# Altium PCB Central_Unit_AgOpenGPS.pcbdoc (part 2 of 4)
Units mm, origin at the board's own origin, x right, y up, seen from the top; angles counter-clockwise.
Board outline 200.19 x 122.57 mm, 2 copper layers (Top Layer, Bottom Layer); 271 components, 213 nets, 1023 pads, 412 vias.
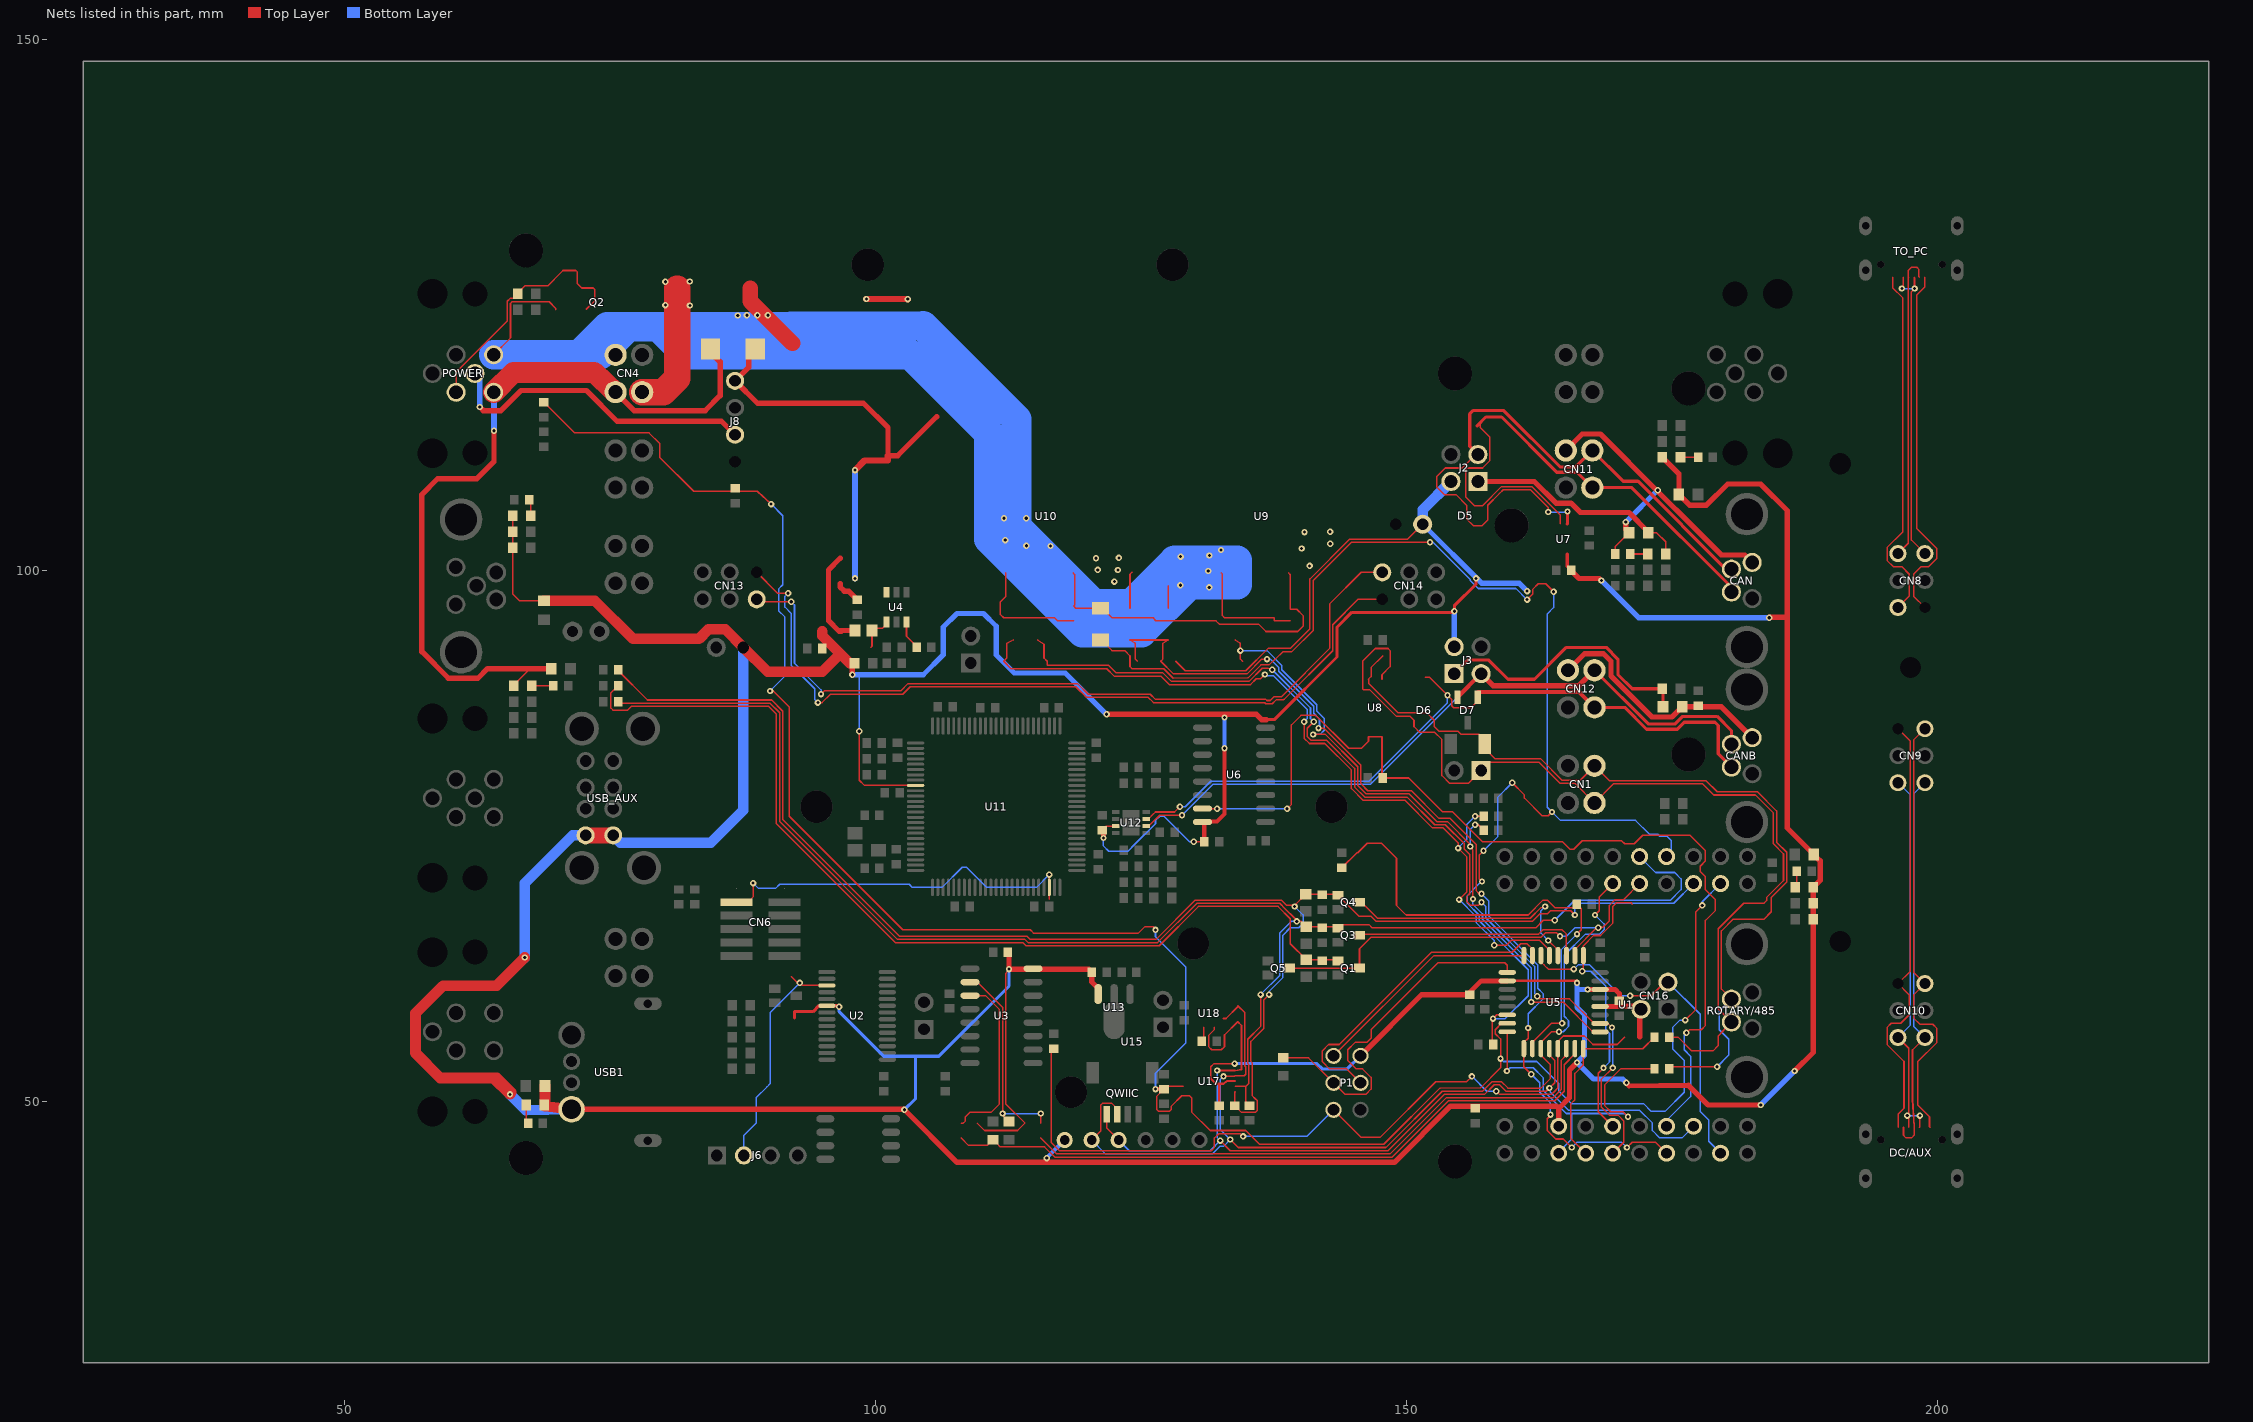
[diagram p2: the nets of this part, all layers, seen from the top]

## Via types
v1: diameter 0.6, hole 0.3, Top Layer to Bottom Layer, 411 vias
v2: diameter 0.61, hole 0.305, Top Layer to Bottom Layer, 1 vias

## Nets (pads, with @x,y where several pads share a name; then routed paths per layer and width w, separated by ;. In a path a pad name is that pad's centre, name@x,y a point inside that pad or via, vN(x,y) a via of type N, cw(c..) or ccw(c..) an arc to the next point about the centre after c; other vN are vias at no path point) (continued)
+5V: 5V.2 C2.1 C4.1 C11.1 C14.1 C22.1 C26.1 C34.1 C35.1 C40.1 C53.1 C56.1 CHA.2 CHB.2 CN7.1 CN16.2 F1.2 F5.1 F6.1 F7.1 FGNSS.1 FROT.1 FSER.1 FWAS.1 J1.2 J2.2 J3.2 L8.2 P1.2 R6.2 R22.2 R23.2 R48.1 U1.31 U2.20 U3.16 U5.4 U5.6 U5.18 U6.16 U7.3 U11.9 U12.3 U13.3 U15.1 U17.8 USB1.1 USB_AUX.1 USB_AUX.5 WAS1.2 WAS2.2 | length 676.7
  Top Layer w0.145: FWAS.1@65.837,105.166 65.837,97.815 66.488,97.165 F5.1@68.786,97.165 ; FGNSS.1@68.837,49.666 68.887,49.716 F1.2@68.887,51.466 ; v1(98.486,84.866) 98.486,80.267 98.987,79.766 U11.9@103.787,79.766 ; R22.2@109.587,47.966 110.287,47.266 110.487,47.266 ; C40.1@121.387,75.566 121.757,75.936 U12.3@122.655,75.936 ; R48.1@128.287,91.466 129.187,90.566 134.887,90.566 136.988,92.667 139.088,92.667 140.937,94.516 140.937,99.218 144.687,102.967 150.158,102.967 J1.2@151.557,104.366 ; v1(129.987,74.466) C4.1@130.987,74.466 ; 131.588,52.167 131.588,53.266 131.887,53.566 v1(133.837,53.566) ; CHB.2@188.337,67.166 188.337,70.166 188.887,70.716 188.887,72.766 F6.1@188.387,73.266
  Top Layer w0.15: 110.487,47.266 113.388,47.266 R23.2@114.087,47.966 112.286,49.766 112.287,62.066 v1(112.587,62.466) 112.632,62.511 U3.16@114.859,62.511
  Top Layer w0.2: 131.587,52.166 132.087,51.666 132.787,51.666 133.138,51.917 U17.8@133.89,51.917 ; C14.1@132.387,49.616 132.387,51.635 132.419,51.666
  Top Layer w0.25: U5.18@159.518,61.356 166.089,61.356 v1(166.087,61.166)
  Top Layer w0.3: C26.1@92.387,57.866 92.388,58.466 94.138,58.466 94.689,59.02 U2.20@95.442,59.018 ; U2.20@95.442,59.018 96.541,59.019 96.587,58.972 v1(96.587,58.916) ; 136.924,85.966 137.587,85.966 143.488,91.867 143.488,94.666 144.887,96.065 148.588,96.065 154.437,96.065 v1(154.537,96.166) 154.537,96.687 156.586,98.737 v1(156.587,99.266) ; U7.3@165.167,101.533 165.167,100.386 C2.1@165.537,100.016
  Top Layer w0.4: U6.16@130.815,76.321 U6.16@130.987,76.149 ; C4.1@130.987,74.466 U6.16@130.987,76.149 ; v1(132.887,83.266) 132.888,77.066 132.187,76.365 130.988,76.365 U6.16@130.988,76.149
  Top Layer w0.45: C22.1@155.987,60.066 155.987,60.267 157.077,61.356 U5.18@159.518,61.356 ; U5.4@168.255,58.948 170.087,58.948 170.087,60.166 169.688,60.546 ; U5.6@168.255,60.546 169.667,60.546
  Top Layer w0.5: 70.087,49.167 70.386,49.266 102.688,49.266 107.686,44.267 148.888,44.267 154.186,49.566 164.148,49.566 164.366,49.347 ; v1(97.837,90.191) 5V.2@97.837,91.266 ; C35.1@112.487,64.066 112.587,63.966 v1(112.587,62.466) 120.087,62.466 C53.1@120.387,62.166 ; C53.1@120.386,62.167 120.386,61.265 120.988,60.665 U13.3@120.988,60.114 ; C40.1@121.387,75.566 121.487,75.466 v1(121.487,74.816) ; v1(121.787,86.466) 135.887,86.466 136.387,85.966 136.837,85.966 ; P1.2@145.699,54.298 151.467,60.066 C22.1@155.987,60.066 ; U1.31@164.366,47.666 164.366,49.347 ; C2.1@165.537,100.016 166.287,99.266 168.187,99.266 v1(168.387,99.066) ; v1@166.086,53.665 165.388,52.967 165.388,50.366 164.366,49.347 ; v1(167.087,60.547) U5.6@168.256,60.547 ; C34.1@170.087,59.466 170.087,58.966 171.885,58.966 171.986,58.865 171.986,56.065 ; v1(170.737,51.766) 170.987,51.466 176.586,51.516 178.438,49.667 v1(183.387,49.666) ; FSER.1@174.137,110.666 175.687,109.116 F7.1@175.687,107.166 176.688,106.167 178.288,106.167 180.287,108.166 183.388,108.166 185.888,105.667 185.888,75.766 F6.1@188.387,73.266 188.987,72.666 188.987,70.816 188.337,70.166 188.337,54.616 ; v1(184.187,95.566) 184.23,95.608 185.888,95.608 ; v1(186.587,52.866) 188.337,54.616 ; 188.337,55.481 188.337,54.616
  Top Layer w1: 63.478,52.215 64.038,52.215 v1(65.587,50.666) ; v1@65.687,50.866 64.339,52.215 59.038,52.215 56.688,54.564 56.688,58.316 59.287,60.917 64.339,60.917 v1(66.987,63.566) ; F5.1@68.786,97.165 73.587,97.165 77.186,93.566 83.386,93.566 84.288,94.465 85.858,94.465 CN7.1@87.557,92.766 89.858,90.465 94.986,90.465 96.688,92.167 ; F1.2@68.887,51.466 68.888,49.566 USB1.1@71.387,49.266 ; 94.987,94.266 94.987,93.866 96.687,92.166 ; 5V.2@97.837,91.266 97.587,91.266 96.687,92.166
  Top Layer w1.5: USB_AUX.1@72.712,75.066 USB_AUX.5@75.313,75.066
  Bottom Layer w0.145: v1(98.486,84.866) 98.486,90.191 ; v1(121.487,74.816) 121.487,74.066 121.987,73.566 123.787,73.566 124.487,74.266 126.387,76.166 126.387,76.466 126.787,76.866 127.187,76.866 127.587,76.466 129.587,74.466 v1(129.987,74.466)
  Bottom Layer w0.3: v1(96.587,58.916) 96.587,58.466 100.787,54.266 105.987,54.266 112.587,60.866 v1(112.587,62.466) ; v1(102.737,49.216) 103.787,50.266 103.787,54.266 ; v1(133.837,53.566) 141.587,53.566 142.087,53.066 144.467,53.066 P1.2@145.699,54.298
  Bottom Layer w0.4: v1(116.137,44.666) U15.1@117.837,46.366 ; v1(132.887,83.266) v1(132.887,86.166)
  Bottom Layer w0.5: v1@97.836,90.19 104.514,90.19 106.388,92.065 106.388,94.666 107.686,95.966 110.188,95.966 111.387,94.765 111.387,92.065 113.086,90.366 117.887,90.366 v1(121.787,86.466) ; J1.2@151.557,104.366 157.107,98.816 160.637,98.816 v1(161.387,98.066) ; J3.2@154.517,92.836 154.537,92.856 v1(154.537,96.166) ; 166.087,60.566 v1(166.087,61.166) ; v1(167.087,60.547) 166.205,60.546 166.086,60.665 166.086,58.867 166.787,58.166 166.787,54.366 166.086,53.665 167.635,52.116 170.386,52.116 v1(170.737,51.766) ; v1(168.387,99.066) 171.887,95.566 v1(184.187,95.566) ; v1(183.387,49.666) v1@186.587,52.866
  Bottom Layer w1: v1(65.587,50.666) 67.087,49.166 USB1.1@71.387,49.266 ; v1(66.987,63.566) 66.988,70.566 71.486,75.065 USB_AUX.1@72.712,75.066 ; USB_AUX.5@75.311,75.065 75.987,74.366 84.486,74.366 87.557,77.437 CN7.1@87.557,92.766 ; J1.2@151.557,104.366 151.557,105.736 J2.2@154.217,108.396
  other v1: 166.087,53.666
+BATT: CN4.2 D3.2 F4.1 FINP.1 POWER.1 | length 76.3
  Top Layer w0.145: FINP.1@65.937,89.166 65.937,89.216 67.487,90.766 F4.1@69.487,90.766
  Top Layer w0.5: v1(64.087,113.166) 64.087,110.267 62.487,108.666 58.786,108.666 57.288,107.165 57.288,92.367 59.787,89.865 62.586,89.865 63.488,90.767 F4.1@69.487,90.766 ; CN4.2@75.538,116.817 77.288,115.067 83.978,115.067 85.388,116.477 85.388,119.665 84.486,120.566 D3.2@84.486,121.067
  Top Layer w2: POWER.1@64.054,116.797 65.924,118.666 73.513,118.666 CN4.2@75.487,116.817
  Bottom Layer w0.6: POWER.1@64.055,116.798 64.087,116.766 v1(64.087,113.166)
+MOTOR: C30.2 C31.1 CN4.1 D1.1 MOT.2 POWER.4 Q2.2 R51.2 R53.2 U9.7 U10.7 | length 43.6
  Top Layer w0.145: POWER.4@60.519,116.798 60.519,118.697 65.337,123.515 65.337,125.367 65.639,125.667 66.338,125.667 MOT.2@66.337,126.066 ; MOT.2@66.338,126.073 66.338,126.167 66.988,126.815 69.137,126.815 70.437,128.115 70.587,128.266 ; R53.2@123.987,96.466 123.988,99.667 C30.2@124.187,99.866
  Top Layer w0.15: 70.587,128.265 71.789,128.265 71.938,128.115 71.938,127.015 72.337,126.617 73.437,126.617 73.587,126.467 73.587,125.423 Q2.2@72.771,124.606
  Top Layer w0.6: v1(99.155,125.578) v1(103.053,125.573)
  Top Layer w2.5: CN4.1@78.037,116.816 80.038,116.817 81.352,118.13 D1.1@81.352,126.566
  other v1: 122.517,98.967 122.842,100.062 120.947,100.072 140.904,100.444 120.779,101.161 122.939,101.198 140.152,102.081 142.842,102.524 140.425,103.624 142.833,103.662 82.535,124.966 80.224,125.004 80.224,127.214 82.522,127.227
+SMPS: C20.2 C21.2 L7.2 L8.1 R17.2 | length 9.5
  Top Layer w0.5: C21.2@96.687,101.166 95.588,100.066 95.588,95.283 96.604,94.267 ; L8.1@96.787,94.266 96.604,94.267 ; R17.2@98.087,94.366 96.703,94.366 96.604,94.267
+VIN: C17.2 C18.2 C19.2 C32.1 D2.1 D3.1 J8.4 U4.3 | length 47.1
  Top Layer w0.5: J8.4@86.787,117.876 88.897,115.766 98.887,115.766 101.187,113.466 101.187,110.816 ; 87.803,116.86 86.792,117.871 88.088,119.167 88.088,120.866 D3.1@88.687,120.866 ; C17.2@96.687,98.766 96.688,98.466 97.087,98.067 97.488,98.067 C19.2@98.287,97.266 ; 101.186,110.815 102.103,110.815 D2.1@105.787,114.501
  Top Layer w0.6: v1(98.087,109.466) 98.987,110.366 101.186,110.366 101.186,110.815
  Bottom Layer w0.6: v1(98.087,99.266) v1(98.087,109.466)
-MOTOR: C30.1 C31.2 CN4.4 D1.2 POWER.2 R11.1 R12.1 R20.2 R21.2 R49.1 R54.2 U9.1 U10.1 | length 213.3
  Top Layer w0.145: POWER.2@64.054,120.335 65.639,121.918 65.639,125.164 65.792,125.316 ; U10.1@112.277,99.782 112.277,97.556 111.787,97.066 111.787,95.866 112.087,95.566 116.888,95.566 R21.2@117.187,95.266 R20.2@118.687,95.266 ; R54.2@127.587,96.466 127.587,98.566 ; U9.1@132.577,99.782 132.688,99.672 132.688,95.766 132.888,95.565 137.587,95.565 R11.1@137.587,95.266 ; R11.1@137.587,95.266 R12.1@139.087,95.266
  Top Layer w0.15: 65.787,125.316 69.287,125.316 69.887,124.716 R49.1@69.887,124.566
  Top Layer w1.5: D1.2@88.222,126.566 88.222,125.381 C31.2@92.187,121.416
  Bottom Layer w2.8: POWER.2@64.054,120.335 74.067,120.335 76.698,122.967 ; 72.162,120.348 74.793,122.979 ; 74.76,122.967 76.698,122.967 ; 79.185,122.967 104.487,123.066 113.287,114.267 113.287,104.165 120.587,96.866 124.087,96.866 128.187,100.965 134.087,100.965 134.087,98.666 129.586,98.666 125.085,94.165 119.487,94.165 110.686,102.967 110.686,112.967 103.287,120.366 82.187,120.366 79.586,122.967 76.698,122.967
  other v1: 131.452,98.425 128.734,98.618 131.349,99.96 128.756,101.316 131.461,101.418 132.555,101.948 116.504,102.317 114.229,102.334 112.229,102.872 112.115,104.932 114.215,104.929 87.04,124.032 87.904,124.045 88.894,124.045 89.885,124.045
.8V: R17.1 R18.2 U4.4 | length 3.5
  Top Layer w0.145: R18.2@99.587,92.766 99.687,92.866 R17.1@99.687,94.366 99.887,94.566 100.687,94.566 101.037,94.915 U4.4@101.037,95.166
_RESET: C7.1 P1.5 R6.1 U5.29 | length 75.3
  Top Layer w0.145: C7.1@116.787,54.966 116.586,54.966 116.586,46.116 117.338,45.367 131.639,45.367 131.938,45.667 131.938,46.566 132.337,46.965 134.389,46.965 v1(134.637,46.716) ; P1.5@143.159,49.218 145.761,46.617 147.536,46.617 152.787,51.867 155.687,51.867 v1@156.188,52.365 ; v1(158.487,50.966) 158.787,50.666 160.387,50.666 163.687,50.666 163.887,50.866 164.281,51.26 U5.29@164.281,54.984 164.281,55.66 164.787,56.166 166.787,56.166 167.587,55.366 169.887,55.366 R6.1@170.587,56.066
  Bottom Layer w0.145: v1(134.637,46.716) 140.657,46.716 P1.5@143.159,49.218 ; v1(156.187,52.366) 157.587,50.966 v1(158.487,50.966)
_RESETNXP: CN6.10 U11.48 | length 35.8
  Top Layer w0.145: CN6.10@86.937,68.771 87.992,68.771 88.487,69.266 v1(88.487,70.566) ; 116.387,69.066 U11.48@116.387,70.166 v1(116.387,71.366)
  Bottom Layer w0.145: v1(88.487,70.566) 88.987,70.066 90.587,70.066 90.988,70.465 103.188,70.465 103.488,70.165 106.287,70.165 108.187,72.065 108.588,72.065 110.488,70.165 115.187,70.165 v1(116.387,71.366)
_RXD: R9.2 RXD.1 U3.2 | length 19.6
  Top Layer w0.145: U3.2@108.915,61.241 109.613,61.241 111.987,58.867 111.987,48.715 RXD.1@112.586,48.115 ; R9.2@115.587,47.966 v1(115.587,48.866)
  Bottom Layer w0.145: v1(111.987,48.866) v1(115.587,48.866)
_TXD: R7.1 U3.3 | length 16.8
  Top Layer w0.145: R7.1@108.087,47.966 108.288,47.965 108.486,48.166 108.486,48.565 108.888,48.966 110.887,48.966 111.687,49.767 111.687,58.666 110.382,59.971 U3.3@108.915,59.971
_URES: J6.2 R34.1 U2.17 | length 22.1
  Top Layer w0.145: R34.1@92.087,61.766 92.688,61.166 v1(92.887,61.166) 93.087,60.966 95.4,60.966 U2.17@95.442,60.923
  Bottom Layer w0.145: J6.2@87.617,44.916 87.617,46.796 88.787,47.966 88.787,50.366 89.787,51.366 90.087,51.666 90.087,52.566 90.087,58.366 v1(92.887,61.166)
A: CN1.4 D6.1 J4.1 R32.1 R37.1 R90.1 ROTARY/485.4 U8.6 | length 90.3
  Top Layer w0.145: R37.1@146.387,91.966 147.087,92.666 148.287,92.666 148.487,92.466 148.487,90.966 147.722,90.201 U8.6@147.722,89.786 ; R37.1@146.387,91.966 145.888,91.465 145.888,88.867 145.987,88.765 146.586,88.765 149.088,86.266 150.386,86.266 150.737,85.916 D6.1@150.737,85.666 150.737,85.316 151.288,84.765 152.688,84.765 153.363,84.089 153.363,80.691 154.087,79.967 155.857,79.967 157.056,81.166 157.056,81.966 162.487,81.966 164.488,79.967 165.888,79.967 CN1.4@167.737,78.116 169.538,79.916 177.912,79.916 178.961,78.867 182.888,78.867 184.587,77.165 184.587,74.265 185.537,73.317 185.537,70.815 183.945,69.223 183.945,68.923 R32.1@183.687,68.666 181.788,68.666 179.388,66.266 179.388,58.74 ROTARY/485.4@180.637,57.491 ; R90.1@174.787,56.066 175.588,56.065 176.886,54.765 178.888,54.765 179.388,55.265 179.388,56.167 ROTARY/485.4@180.427,57.28
A0/WAS: C9.2 R13.1 R97.2 U1.6 U5.23 U17.4 | length 208
  Top Layer w0.145: R97.2@68.787,115.866 71.687,112.966 78.687,112.966 79.687,111.966 79.687,110.666 82.888,107.465 87.934,107.465 ; R13.1@86.787,107.766 86.787,107.465 88.887,107.466 v1(90.187,106.266) ; v1(90.087,88.666) 90.386,88.666 91.888,87.165 91.888,76.866 102.586,66.167 114.588,66.167 114.887,65.865 124.304,65.863 ; 124.306,65.862 124.783,65.862 125.39,66.469 126.183,66.469 126.388,66.266 v1(126.387,66.166) ; C9.2@127.186,51.166 126.487,50.465 126.487,49.266 126.688,49.065 127.686,49.065 127.887,49.266 127.887,49.566 128.862,50.541 129.594,50.541 129.787,50.345 129.787,49.017 131.537,47.267 134.887,47.267 136.188,45.966 147.889,45.966 153.188,51.265 156.993,51.273 158.888,53.167 158.888,55.885 158.387,56.386 158.387,56.767 158.982,57.358 U5.23@159.518,57.358 ; C9.2@127.187,51.166 127.438,51.417 U17.4@128.988,51.416 ; v1(176.287,57.666) 177.287,58.666 177.287,67.866 v1(177.887,68.466)
  Top Layer w0.4: v1(126.387,51.166) C9.2@127.187,51.166
  Bottom Layer w0.145: v1(90.087,88.666) 91.486,90.066 91.486,95.623 90.887,96.223 90.887,98.265 91.288,98.666 91.288,105.166 v1(90.187,106.266) ; v1(126.387,51.166) 126.388,52.667 129.238,55.517 129.238,62.667 126.388,65.514 v1(126.387,66.166) ; v1(158.888,54.038) 159.159,53.767 162.286,53.767 164.387,51.666 164.387,50.968 165.588,49.766 172.388,49.766 173.086,49.065 174.387,49.065 176.188,50.866 176.188,53.866 175.088,54.966 175.088,56.967 175.786,57.666 v1(176.287,57.666) ; v1(177.887,68.466) 177.887,68.806 U1.6@179.607,70.526
A1/CH_B: R91.2 U1.32 U5.24 | length 33.5
  Top Layer w0.145: v1(159.487,52.866) 159.518,52.866 U5.24@159.518,56.559 ; v1(170.887,48.566) 170.412,49.041 169.262,49.041 168.687,49.616 168.687,51.565 170.188,53.066 R91.2@173.386,53.066
  Bottom Layer w0.145: v1(159.487,52.866) 159.792,53.17 161.966,53.17 162.888,52.248 162.888,51.067 165.085,48.867 166.452,48.867 ; U1.32@164.366,45.787 164.366,45.126 164.366,45.245 165.588,46.467 165.588,48.867 170.587,48.867 v1(170.887,48.566)
A2/SAFESENSE: R25.1 R48.2 R53.1 R54.1 U1.16 U5.25 | length 93.3
  Top Layer w0.145: R25.1@124.687,91.466 124.486,91.666 124.486,93.165 R53.1@123.987,93.466 R54.1@127.587,93.466 127.087,93.165 127.087,91.666 126.886,91.465 128.085,90.267 135.007,90.267 136.406,91.666 v1@136.886,91.666 ; v1(141.737,85.166) 142.238,85.166 145.738,81.666 145.738,79.916 146.388,79.266 150.488,79.266 153.089,76.665 154.148,76.665 156.586,74.224 156.586,69.865 156.886,69.566 v1(157.087,69.566) ; v1@161.486,56.916 161.486,55.966 161.082,55.563 161.082,54.983 161.083,53.27 v1(161.787,52.566) ; v1(163.587,48.766) 163.587,48.666 163.287,48.367 163.287,47.267 164.087,46.467 164.788,46.467 v1(165.587,45.666) ; v1(170.787,45.666) 171.287,46.166 171.587,46.166 173.487,46.166 U1.16@174.527,45.126
  Bottom Layer w0.145: v1@136.886,91.666 137.186,91.666 137.986,90.866 137.986,90.516 141.288,87.216 141.288,86.566 141.837,86.017 141.837,85.217 141.887,85.166 v1(141.737,85.166) ; v1(157.087,69.566) 157.788,68.865 157.788,67.465 162.388,62.865 162.388,60.665 162.888,60.165 162.888,59.665 161.486,58.265 v1@161.486,56.916 ; v1(161.787,52.566) 162.587,51.766 162.588,50.864 163.587,49.865 v1(163.587,48.766) ; v1(165.587,45.666) 166.089,46.167 170.287,46.167 v1(170.787,45.666)
  other v1: 161.487,56.916 136.887,91.666
A3/OUT: R33.2 R77.1 R94.2 U5.26 | length 45.6
  Top Layer w0.145: R77.1@143.937,72.016 145.337,73.416 R33.2@145.437,73.416 146.337,74.316 147.686,74.315 149.088,72.913 149.088,70.665 ; 149.087,70.666 149.087,68.466 149.987,67.566 161.487,67.566 162.887,68.966 163.296,68.966 163.996,68.266 166.387,68.266 166.487,68.166 166.487,66.166 v1(166.087,65.766) ; U5.26@161.883,54.984 161.883,55.562 163.687,57.366 v1(164.687,57.366)
  Bottom Layer w0.145: v1(164.687,57.366) 164.587,57.366 164.587,64.267 v1(166.087,65.766)
A4/SDA: QWIIC.3 R30.1 U1.22 U5.27 U15.2 U17.9 U18.6 | length 95.1
  Top Layer w0.145: U15.2@120.376,46.365 121.237,47.226 121.237,49.665 121.387,49.817 122.286,49.817 122.787,49.317 QWIIC.3@122.787,48.816 ; v1(132.787,52.366) 133.84,52.366 U17.9@133.89,52.416 134.738,52.417 134.887,52.566 134.887,53.266 134.787,53.366 134.787,58.369 R30.1@134.139,59.017 134.139,58.918 133.038,57.817 U18.6@132.789,57.817 ; v1(133.437,46.416) 134.186,45.667 148.088,45.667 153.386,50.965 157.188,50.965 158.09,51.867 158.987,51.867 159.589,51.265 162.685,51.265 163.587,52.167 163.587,53.465 162.682,54.369 U5.27@162.682,54.983 ; U5.27@162.683,54.984 162.683,55.562 163.687,56.566 v1(164.387,56.566) ; v1(167.787,67.566) 168.187,67.966 168.187,69.266 U1.22@169.446,70.526
  Bottom Layer w0.145: U15.2@120.377,46.366 121.677,45.066 131.737,45.066 132.437,45.766 132.787,45.766 v1(133.437,46.416) 132.487,47.366 132.487,52.065 v1@132.787,52.365 ; v1(164.387,56.566) 164.788,56.566 165.288,57.066 165.288,57.62 164.887,58.021 164.887,63.767 166.886,65.766 168.171,65.766 168.237,65.766 168.637,66.166 168.637,66.716 v1(167.787,67.566)
A5/SCL: QWIIC.4 R29.1 U1.11 U5.28 U15.3 U17.10 U18.4 | length 88.6
  Top Layer w0.145: QWIIC.4@121.787,48.816 121.787,47.496 U15.3@122.917,46.366 ; 131.938,56.967 131.938,56.769 131.387,56.215 131.387,55.166 131.687,54.867 132.586,54.867 132.888,55.166 132.888,56.264 R29.1@134.139,57.517 ; v1(132.187,52.916) U17.10@133.89,52.917 134.488,53.014 134.488,57.169 134.14,57.517 ; v1(132.487,46.316) 133.437,45.367 148.288,45.367 153.587,50.665 157.387,50.665 158.288,51.567 158.786,51.567 159.388,50.965 163.185,50.965 v1(163.487,51.266) 163.983,51.763 163.983,53.868 163.483,54.369 U5.28@163.483,54.983
  Bottom Layer w0.145: U15.3@122.917,46.366 123.917,45.366 131.537,45.366 v1(132.487,46.316) 132.187,46.616 v1(132.187,52.916) ; v1(163.487,51.266) 163.587,50.866 165.286,49.167 171.986,49.167 173.188,47.965 173.188,47.267 173.886,46.566 175.967,46.566 U1.11@177.066,47.666
A7/CURRSEN: C57.2 R28.1 U1.13 U5.22 | length 130
  Top Layer w0.145: R28.1@121.187,93.466 121.288,93.467 122.286,92.466 123.488,92.466 123.988,91.966 123.988,90.965 124.186,90.767 127.163,90.767 128.065,89.865 135.09,89.888 136.317,91.115 137.087,91.115 138.39,92.37 139.241,92.37 141.237,94.366 141.237,99.065 144.836,102.667 v1(152.237,102.667) ; v1(157.137,70.716) 156.884,70.969 156.884,73.212 v1(157.287,73.616) ; C57.2@158.336,55.116 158.288,55.065 158.088,55.265 158.088,57.716 v1(158.176,57.805) 158.53,58.158 U5.22@159.518,58.158 ; v1(159.987,80.016) 161.137,78.866 161.137,78.574 162.796,76.916 163.387,76.916 v1(163.737,77.266) ; v1(161.387,97.266) 161.937,97.816 161.937,98.266 162.437,98.766 163.137,98.766 v1(163.887,98.016)
  Bottom Layer w0.145: v1(152.237,102.667) 152.536,102.667 154.537,100.666 156.037,99.166 156.037,99.066 156.787,98.316 157.637,98.316 160.337,98.316 v1(161.387,97.266) ; v1(157.137,70.716) 156.987,70.566 156.937,70.566 155.737,69.366 155.737,68.697 156.887,67.547 156.887,67.016 157.987,65.916 161.486,62.417 161.486,59.967 159.327,57.805 v1(158.176,57.805) ; v1(157.287,73.616) 158.637,74.966 158.637,78.666 v1(159.987,80.016) ; v1@163.886,98.016 163.886,96.515 163.284,95.913 163.284,77.719 164.537,76.467 171.608,76.467 172.906,75.166 173.688,75.166 173.886,74.966 174.587,74.966 174.986,74.567 174.986,73.525 U1.13@174.526,73.066
A/RTSW: C24.2 C27.2 Q4.1 R36.2 R40.2 U1.10 U17.6 | length 149.5
  Top Layer w0.145: R40.2@75.787,90.666 75.786,90.566 78.537,87.815 90.237,87.816 ; 90.237,87.815 91.288,86.764 91.288,76.563 102.286,65.565 114.288,65.565 114.588,65.265 126.437,65.265 130.14,68.969 138.237,68.969 138.74,68.466 139.482,68.466 R36.2@140.53,69.515 143.482,69.515 Q4.1@143.571,69.426 145.532,67.465 146.668,67.465 147.168,66.967 161.887,66.967 162.586,67.666 163.287,67.666 163.587,67.965 165.489,67.965 v1(165.887,67.566) ; C24.2@133.838,49.616 134.491,48.966 135.786,48.966 135.987,49.167 135.987,50.066 135.787,50.266 135.487,50.566 135.487,52.066 135.487,53.666 135.381,53.772 135.381,55.66 135.887,56.166 136.587,56.866 136.587,57.366 136.587,59.566 v1(137.087,60.066) ; C24.2@133.839,49.617 133.839,50.866 U17.6@133.89,50.917
  Bottom Layer w0.145: v1(137.087,60.066) 137.087,60.366 138.387,61.666 138.387,65.667 139.086,66.365 139.888,66.365 140.287,66.767 140.287,67.567 v1(139.487,68.366) ; v1(165.887,67.566) 165.888,68.466 166.086,68.666 175.207,68.666 U1.10@177.066,70.526
A/WKSW: C25.2 C29.2 Q3.1 R45.2 R47.2 U1.17 U17.7 | length 146.9
  Top Layer w0.145: R45.2@75.787,87.666 75.786,87.516 90.087,87.516 90.988,86.614 90.988,76.365 102.088,65.265 114.087,65.265 114.387,64.966 126.586,64.966 130.292,68.672 138.083,68.672 138.588,68.166 ; 133.889,51.417 134.887,51.417 ; C25.2@135.239,49.617 134.887,49.969 134.887,51.417 ; v1(136.287,60.066) 136.287,57.066 135.084,55.863 135.084,53.569 135.187,53.466 135.187,53.166 135.187,51.717 134.887,51.417 ; 138.359,68.395 139.687,67.067 v1(139.687,66.966) ; v1@139.688,66.965 140.089,66.965 R47.2@140.587,66.466 ; R47.2@140.587,66.466 143.431,66.466 Q3.1@143.571,66.326 ; Q3.1@143.571,66.326 143.693,66.327 144.031,66.665 146.487,66.665 146.787,66.365 162.218,66.365 162.919,67.066 v1(163.987,67.066)
  Bottom Layer w0.145: v1(136.287,60.066) 138.087,61.866 138.087,65.866 139.187,66.966 v1(139.687,66.966) ; v1(163.987,67.066) 165.885,68.964 174.885,68.964 175.888,69.967 175.888,70.965 175.288,71.567 173.488,71.567 U1.17@171.986,73.066
AUX: J8.2 POWER.5 | length 30
  Top Layer w0.5: v1(62.737,115.416) 63.086,115.065 64.737,115.065 66.64,116.967 72.787,116.967 75.687,114.066 85.517,114.066 J8.2@86.787,112.796
  Bottom Layer w0.5: POWER.5@62.287,118.566 62.737,118.116 v1(62.737,115.416)
B: CN1.2 D6.2 R31.1 R38.1 R91.1 R92.2 ROTARY/485.2 U8.7 | length 83.8
  Top Layer w0.145: U8.7@146.452,89.786 146.688,90.02 146.688,90.866 R38.1@147.787,91.966 ; U8.7@146.452,89.786 146.452,89.401 149.259,86.595 151.958,86.595 152.637,85.916 D6.2@152.637,85.666 ; D6.2@152.637,85.666 152.637,85.316 153.086,84.867 154.887,84.867 155.187,84.567 156.886,84.567 157.387,84.066 R92.2@157.387,83.666 ; R92.2@157.087,82.865 157.785,82.865 158.387,82.266 162.687,82.266 164.686,80.267 166.386,80.267 CN1.2@167.737,81.616 169.137,80.216 173.554,80.216 173.58,80.216 ; 173.237,80.216 173.188,80.216 178.237,80.216 179.286,79.167 183.086,79.167 184.887,77.366 184.887,74.417 185.837,73.467 185.837,70.665 184.387,69.215 184.387,67.866 R31.1@183.687,67.166 180.787,67.166 179.687,66.066 179.687,60.591 ROTARY/485.2@180.637,59.641 ; R91.1@174.787,53.066 174.788,53.266 v1(179.287,53.266)
  Bottom Layer w0.145: v1(179.287,53.266) 180.386,54.366 180.386,55.867 179.487,56.767 179.487,58.489 ROTARY/485.2@180.638,59.639
C8_2: C8.2 U18.2 | length 1.4
  Top Layer w0.145: C8.2@130.737,55.666 130.939,55.868 U18.2@130.939,56.967
C16_1: C16.1 U4.6 | length 2.8
  Top Layer w0.145: U4.6@102.937,95.166 102.937,93.817 103.887,92.866 C16.1@103.887,92.766
C28_2: C28.2 Q1.1 R41.2 R44.2 | length 91.7
  Top Layer w0.145: R41.2@75.787,89.166 75.088,88.466 75.088,87.066 75.286,86.866 76.688,86.866 77.036,87.216 89.937,87.216 ; 90.087,87.066 89.937,87.216 ; R44.2@140.587,63.366 139.088,64.867 139.088,67.216 137.938,68.367 130.437,68.367 126.736,64.666 114.186,64.666 113.886,64.966 101.888,64.966 90.686,76.167 90.686,86.467 89.937,87.216 ; R44.2@140.587,63.366 143.431,63.366 Q1.1@143.571,63.226
CAN+: CAN.1 CN11.1 F2.2 R71.2 | length 31.2
  Top Layer w0.145: R71.2@169.687,101.566 169.687,102.266 F2.2@170.987,103.566
  Top Layer w0.5: CN11.1@165.037,111.316 166.586,112.865 168.288,112.865 170.988,110.165 ; v1(170.687,104.566) 170.687,103.866 F2.2@170.987,103.566 ; CAN.1@182.587,100.766 181.887,101.465 179.683,101.465 171.036,110.112 ; 170.988,110.165 171.036,110.112 ; 170.988,110.165 171.036,110.112
  Bottom Layer w0.5: v1(170.687,104.566) v1(173.687,107.566)
CANB+: CANB.1 CN12.1 F3.2 R72.2 | length 22.9
  Top Layer w0.5: CN12.1@165.237,90.616 166.787,92.167 168.588,92.167 169.286,91.465 169.286,90.066 173.137,86.215 175.037,86.215 F3.2@175.987,87.166 179.688,87.165 CANB.1@182.588,84.265
CANH: CAN.4 CN11.4 D5.2 R60.1 U7.7 | length 52.3
  Top Layer w0.145: D5.2@156.787,106.116 156.437,106.116 155.588,106.967 155.588,109.472 155.784,109.667 157.188,109.667 157.887,110.366 157.887,112.565 156.988,113.467 R60.1@156.987,113.766
  Top Layer w0.15: D5.2@156.787,106.116 157.178,106.116 158.979,107.917 161.837,107.917 164.506,105.248 164.506,104.399
  Top Layer w0.3: 156.698,113.652 157.511,114.465 158.987,114.465 164.186,109.266 166.089,109.266 CN11.4@167.537,107.816 171.237,107.815 180.638,98.415 CAN.4@180.637,97.991
CANH1: CANB.4 CN12.4 D7.1 R65.1 U12.7 | length 70.1
  Top Layer w0.145: U12.7@125.52,76.596 125.717,76.596 126.187,77.066 126.387,77.266 127.187,77.266 128.187,77.266 v1(128.687,77.766) ; R65.1@151.787,89.966 152.187,89.966 154.287,87.866 154.287,87.266 154.487,87.066 156.087,87.066 156.737,87.716 D7.1@156.737,88.066
  Top Layer w0.3: CN12.4@167.737,87.116 170.087,87.117 170.587,87.117 172.637,85.065 175.537,85.065 176.188,85.715 179.088,85.715 179.388,85.415 179.388,82.741 CANB.4@180.637,81.491
  Top Layer w0.4: D7.1@156.737,88.066 156.79,88.565 166.289,88.565 CN12.4@167.737,87.116
  Bottom Layer w0.145: v1@128.687,77.765 129.187,77.765 131.588,80.165 146.487,80.165 153.886,87.564 v1(153.887,88.266)
CANL: CAN.2 CN11.2 D5.1 J2.3 U7.6 | length 61.2
  Top Layer w0.145: J2.3@156.757,110.936 156.558,110.937 155.288,109.667 153.688,109.667 152.888,108.867 152.888,107.866 153.587,107.165 154.686,107.165 155.687,106.167 155.687,104.867 156.337,104.216 D5.1@156.787,104.216 157.138,104.216 157.686,104.765 157.686,106.165 158.787,107.266 159.139,107.618 161.712,107.618 163.387,105.943 v1(163.387,105.516)
  Top Layer w0.3: J2.3@156.757,110.936 155.987,111.706 155.987,114.765 156.287,115.067 159.187,115.067 164.488,109.766 165.987,109.766 167.536,111.316 170.437,108.415 171.839,108.415 180.112,100.142 CAN.2@180.637,100.141 ; U7.6@165.167,104.398 165.187,104.418 v1(165.187,105.566)
  Bottom Layer w0.145: v1(163.387,105.516) 165.137,105.516 v1(165.187,105.566)
CANL1: CANB.2 CN12.2 D7.2 J3.3 U12.6 | length 70.1
  Top Layer w0.145: U12.6@125.52,75.936 125.757,75.936 126.087,76.266 126.787,76.966 v1(128.887,76.966)
  Top Layer w0.3: CN12.2@167.737,90.616 172.789,85.565 175.337,85.565 176.038,86.266 179.286,86.266 180.638,84.915 CANB.2@180.638,83.64
  Top Layer w0.4: D7.2@154.836,88.067 J3.3@157.056,90.297 ; D7.2@154.837,88.066 155.241,88.473
  Top Layer w0.5: J3.3@157.057,90.296 158.187,89.166 166.286,89.166 CN12.2@167.737,90.616
  Bottom Layer w0.145: v1(128.887,76.966) 131.786,79.865 146.625,79.865 J3.3@157.056,90.297
CC11: CN8.1 TO_PC.A5 | length 34
  Top Layer w0.145: TO_PC.A5@198.837,127.651 198.837,126.716 198.087,125.966 198.087,103.966 199.987,102.066 199.987,101.166 199.187,100.366 198.487,100.366 197.787,99.666 197.787,97.596 CN8.1@198.857,96.526
CC12: CN9.1 CN10.1 DC/AUX.A5 | length 41.2
  Top Layer w0.145: CN10.1@196.317,61.106 197.386,60.036 197.386,58.166 196.586,57.366 195.687,57.366 195.288,56.967 195.288,55.367 196.886,53.767 196.887,49.366 196.337,48.816 DC/AUX.A5@196.337,47.581 ; CN9.1@196.317,85.106 197.487,83.936 197.487,62.276 CN10.1@196.317,61.106
CC21: CN8.2 TO_PC.B5 | length 33.9
  Top Layer w0.145: TO_PC.B5@195.837,127.651 195.837,126.617 196.787,125.667 196.787,103.665 195.288,102.166 195.288,100.965 195.888,100.366 196.688,100.366 197.386,99.667 197.386,97.597 CN8.2@196.317,96.526
CC22: CN9.2 CN10.2 DC/AUX.B5 | length 41.7
  Top Layer w0.145: CN10.2@198.857,61.106 197.788,60.036 197.788,57.866 198.387,57.267 199.586,57.267 199.987,56.866 199.987,55.565 198.187,53.764 198.187,49.667 199.286,48.565 199.286,47.63 DC/AUX.B5@199.337,47.581 ; CN9.2@198.857,85.106 197.787,84.036 197.787,62.176 CN10.2@198.857,61.106
CN13_1: CN13.1 CN14.1 | length 75.5
  Top Layer w0.145: CN13.1@88.827,99.836 90.797,97.866 v1(91.787,97.866) ; v1(94.587,87.566) 94.986,87.567 95.786,88.367 102.586,88.367 103.287,89.065 118.885,89.065 119.883,88.067 125.687,88.067 126.188,87.567 135.388,87.567 136.668,87.567 136.767,87.465 137.387,87.465 137.747,87.826 138.448,87.826 138.512,87.889 ; 138.486,87.866 143.084,92.464 143.084,94.912 145.469,97.297 CN14.1@147.747,97.296
  Bottom Layer w0.145: v1(91.787,97.866) 91.486,97.567 91.486,96.566 92.088,95.964 92.088,91.067 94.288,88.867 94.288,87.866 v1(94.587,87.566)
CN13_2: CN13.2 CN14.2 | length 74.6
  Top Layer w0.145: CN13.2@88.827,97.296 89.057,97.066 v1(92.087,97.066) ; v1(94.887,88.366) 95.187,88.666 102.388,88.666 103.086,89.365 119.05,89.365 120.049,88.367 125.888,88.367 126.388,87.866 136.787,87.866 136.886,87.767 137.188,87.767 137.544,88.123 138.245,88.123 142.787,92.667 142.787,96.866 145.758,99.837 CN14.2@147.747,99.836
  Bottom Layer w0.145: v1(92.087,97.066) 92.387,96.766 92.387,91.266 94.887,88.766 v1(94.887,88.366)
CURRENTSENSE: R12.2 R20.1 R28.2 U9.6 U10.6 | length 32
  Top Layer w0.145: R20.1@118.687,96.666 118.887,96.466 R28.2@121.187,96.466 ; R28.2@121.187,96.466 121.387,96.467 122.286,95.565 126.172,95.565 126.416,95.265 132.088,95.265 132.388,94.966 136.086,94.966 136.787,94.267 139.787,94.267 140.287,94.765 140.287,95.766 139.688,96.365 139.088,96.365 139.088,96.667 ; U9.6@138.927,99.782 139.087,99.622 139.087,96.666
  Top Layer w0.15: U10.6@118.627,99.782 118.787,99.622 118.787,96.766 R20.1@118.687,96.666
D0/RX: R9.1 U5.30 | length 56.2
  Top Layer w0.145: R9.1@115.587,46.566 117.087,45.065 148.486,45.065 153.787,50.366 163.843,50.366 164.587,51.11 164.587,53.866 165.08,54.359 U5.30@165.08,54.983
D1/TX: R7.2 TXD.1 U5.31 | length 65
  Top Layer w0.145: R7.2@108.087,46.566 108.787,45.866 110.537,45.866 TXD.1@111.087,46.416 111.138,46.416 111.763,45.715 115.941,45.715 116.894,44.765 148.687,44.765 153.988,50.066 163.988,50.066 164.887,50.965 164.887,53.467 165.88,54.46 U5.31@165.88,54.983
D2/CH_A: R90.2 U1.28 U5.32 | length 18.1
  Top Layer w0.145: U5.32@166.68,54.966 172.286,54.966 R90.2@173.386,56.065 ; U5.32@166.68,54.983 166.68,53.437 165.888,52.644 165.888,50.168 165.487,49.766 165.487,46.546 U1.28@166.906,45.126
D3/PWM0: R27.1 R55.1 R95.2 U5.1 | length 64.2
  Top Layer w0.145: R55.1@133.887,93.466 134.387,93.165 134.387,91.666 R27.1@134.587,91.466 ; v1(141.237,84.566) 142.388,84.567 145.438,81.516 145.438,79.766 146.236,78.966 150.285,78.966 152.883,76.368 153.886,76.368 156.038,74.216 v1(156.037,74.016) 156.287,73.666 156.287,72.784 ; v1(156.287,69.066) 156.287,72.967 ; v1(156.487,76.066) 156.787,76.066 R95.2@157.287,75.566 ; v1(161.787,59.366) 164.788,59.365 167.605,56.548 U5.1@168.255,56.548
  Bottom Layer w0.145: v1(134.387,92.466) 136.886,92.466 138.283,91.069 138.283,90.67 141.585,87.368 141.585,86.769 142.286,86.065 142.286,84.966 141.887,84.567 v1(141.237,84.566) ; v1(156.037,74.016) 156.037,75.616 v1(156.487,76.066) ; v1(156.287,69.066) 156.287,68.565 157.188,67.666 157.188,67.165 161.788,62.565 v1(161.787,59.366)
D4/INH: R42.1 R61.1 U1.24 U5.2 | length 94.2
  Top Layer w0.145: R61.1@115.287,93.466 115.887,93.066 115.887,91.766 R42.1@116.187,91.466 116.188,91.067 121.987,91.067 122.688,90.366 127.087,90.366 127.887,89.566 135.187,89.566 136.437,90.815 136.988,90.815 v1(137.387,90.666) ; v1(141.287,85.766) 140.683,85.161 140.683,84.366 141.034,84.016 142.487,84.016 145.136,81.366 145.136,79.616 146.086,78.666 150.087,78.666 152.688,76.065 153.688,76.065 155.487,74.267 155.487,73.767 155.987,73.266 155.987,69.566 155.687,69.266 155.687,68.867 156.086,68.466 156.787,68.466 v1(157.087,68.766) ; v1(162.337,59.916) 162.588,59.665 165.387,59.665 167.704,57.348 U5.2@168.255,57.348 ; U5.2@168.256,57.349 169.004,57.349 v1(169.387,56.966) ; U1.24@169.446,45.126 170.488,46.167 170.488,48.166 169.939,48.715 169.137,48.715 168.387,49.467 168.387,49.865 168.387,52.106 v1(169.447,53.166)
  Bottom Layer w0.145: v1(137.387,90.666) 140.988,87.064 140.988,86.063 v1@141.288,85.763 ; v1(157.087,68.766) 157.488,68.364 157.488,67.315 162.088,62.715 162.088,60.165 v1(162.337,59.916) ; v1(169.387,56.966) 169.447,56.906 v1@169.447,53.166
D5/SERVO: R59.1 U1.23 U5.9 | length 26.9
  Top Layer w0.145: v1(166.587,62.266) 166.691,62.37 U5.9@166.691,63.747 ; U5.9@166.691,63.746 166.691,64.671 167.653,65.634 168.303,65.634 169.436,66.767 169.436,68.346 169.812,68.722 171.186,68.722 R59.1@171.287,68.566 ; v1(168.587,53.166) 168.088,52.667 168.088,49.026 U1.23@169.447,47.666
  Bottom Layer w0.145: v1(166.587,62.266) 167.387,62.266 168.787,60.866 168.786,56.785 169.15,56.42 169.15,53.729 v1(168.587,53.166)
D6/STSW: Q1.3 Q5.3 U1.18 U5.10 | length 42.2
  Top Layer w0.145: Q5.3@139.003,62.566 Q1.3@145.603,62.566 145.603,64.381 146.688,65.466 162.685,65.466 163.094,65.872 164.181,65.872 v1(164.487,65.566) ; U5.10@165.89,63.746 165.89,64.32 167.836,66.266 167.988,66.266 v1(168.087,66.366) 168.037,66.416 168.537,66.416 169.137,67.015 169.137,68.466 169.69,69.019 170.48,69.019 U1.18@171.986,70.526
  Bottom Layer w0.145: v1(164.487,65.566) 165.087,65.566 165.887,66.366 v1(168.087,66.366)
D7/WKSW: Q3.3 U5.11 | length 21.9
  Top Layer w0.145: Q3.3@145.603,65.666 145.703,65.766 162.469,65.766 162.873,66.17 164.684,66.17 165.09,65.763 U5.11@165.09,63.746
D8/RTSW: Q4.3 U5.12 | length 24
  Top Layer w0.145: Q4.3@145.603,68.766 145.786,68.765 147.287,67.267 161.689,67.267 162.687,68.266 v1@163.086,68.367 ; v1(163.387,65.166) 164.291,64.262 U5.12@164.291,63.747
  Bottom Layer w0.145: v1@163.086,68.367 162.687,67.966 162.687,65.866 v1(163.387,65.166)
  other v1: 163.087,68.366
D9/PWM1: R26.1 R62.2 R96.2 U5.13 | length 78.4
  Top Layer w0.145: R62.2@112.987,93.466 112.388,93.165 112.388,91.765 R26.1@112.087,91.466 112.787,90.767 121.788,90.767 122.489,90.066 126.886,90.066 127.686,89.266 135.337,89.266 135.888,89.817 ; 135.889,89.818 136.29,89.818 v1(136.687,90.216) ; v1@140.386,85.766 140.386,84.216 140.884,83.718 142.334,83.718 144.836,81.217 144.836,79.467 145.936,78.367 149.886,78.367 152.487,75.766 153.488,75.766 154.887,74.366 v1(154.887,73.866) 155.687,73.066 155.687,69.716 v1(154.987,69.016) ; v1(156.487,76.866) R96.2@157.287,76.866 ; v1(158.287,64.716) 159.436,64.717 159.888,65.166 162.588,65.166 163.493,64.249 U5.13@163.493,63.746
  Bottom Layer w0.145: v1@136.688,90.117 137.488,90.117 140.686,86.916 140.686,86.065 v1@140.46,85.839 ; v1(154.887,73.866) 155.687,74.666 155.687,76.065 v1(156.487,76.866) ; v1(154.987,69.016) 156.587,67.417 156.587,66.868 158.288,65.166 v1(158.287,64.716)
  other v1: 140.387,85.766
D10: CN16.3 U1.8 U5.14 | length 32.9
  Top Layer w0.145: U5.14@162.693,63.747 162.693,63.16 162.987,62.866 163.387,62.466 v1(165.787,62.466) ; v1(171.087,59.966) 173.086,59.967 174.356,61.237 CN16.3@174.656,61.237
  Bottom Layer w0.145: v1(165.787,62.466) 166.187,62.866 167.289,62.866 170.188,59.967 v1(171.087,59.966) ; CN16.3@174.656,61.237 177.686,58.207 177.686,49.065 178.486,48.265 178.486,46.246 U1.8@179.606,45.126
D11/MOSI: P1.4 U5.15 | length 30.3
  Top Layer w0.145: P1.4@145.699,51.758 144.392,53.066 142.787,53.066 142.088,53.767 142.088,54.765 142.688,55.367 143.688,55.367 152.388,64.066 159.987,64.066 160.788,64.867 161.387,64.867 161.892,64.359 U5.15@161.892,63.746
D12/MISO: P1.1 U5.16 | length 21.8
  Top Layer w0.145: P1.1@143.159,54.298 152.608,63.747 U5.16@161.093,63.747
D13/SCK: LED.1 P1.3 U5.17 | length 34.5
  Top Layer w0.145: LED.1@138.429,54.108 140.809,54.108 P1.3@143.159,51.758 144.252,50.665 146.188,50.665 146.688,51.166 146.688,52.266 145.888,53.066 145.288,53.066 144.488,53.866 144.488,54.867 145.187,55.565 146.287,55.565 146.688,55.966 146.688,56.767 152.987,63.066 159.286,63.066 159.518,62.835 U5.17@159.518,62.156
DIR485: R93.1 U1.15 U6.15 U8.2 U8.3 | length 95.2
  Top Layer w0.145: U6.15@130.815,77.591 131.412,77.591 131.437,77.566 v1(132.187,77.566) ; v1(138.787,77.566) 139.187,77.966 139.187,85.466 140.087,86.365 141.489,86.365 144.585,83.266 145.786,83.266 146.452,83.932 U8.2@146.452,84.346 ; U8.2@146.452,84.346 U8.3@147.722,84.346 147.722,80.531 R93.1@147.787,80.466 ; R93.1@147.787,80.466 150.247,80.467 153.409,77.292 154.361,77.292 157.188,74.465 164.727,74.465 165.426,73.767 165.786,73.767 166.586,74.567 170.287,74.567 170.587,74.267 171.489,74.267 172.286,75.065 176.736,75.065 178.187,73.617 178.187,72.664 177.686,72.167 177.686,71.666 178.187,71.166 178.187,69.944 179.088,69.045 179.088,67.945 178.187,67.046 178.187,57.165 177.788,56.767 176.688,56.767 v1(176.387,56.466)
  Bottom Layer w0.145: v1(132.187,77.566) v1(138.787,77.566) ; U1.15@174.526,47.666 174.526,48.207 176.787,50.467 176.787,54.262 176.188,54.867 176.188,56.266 v1(176.387,56.466)
DN1: CN8.6 TO_PC.A7 TO_PC.B7 | length 29.1
  Top Layer w0.145: CN8.6@196.317,101.606 197.287,102.576 197.287,127.601 ; TO_PC.A7@197.337,127.651 197.287,127.601 ; 198.337,127.651 198.287,127.701 198.287,128.366 198.087,128.566 197.587,128.566 197.287,128.266 197.287,127.601
DN2: CN9.6 CN10.6 DC/AUX.A7 DC/AUX.B7 | length 36.6
  Top Layer w0.145: DC/AUX.B7@196.837,47.581 196.838,46.817 197.087,46.566 197.587,46.566 197.836,46.815 197.836,47.582 197.687,50.266 197.686,54.856 CN10.6@198.857,56.026
  Bottom Layer w0.145: CN9.6@198.857,80.026 197.787,78.956 197.787,57.096 CN10.6@198.857,56.026
DP1: CN8.5 TO_PC.A6 TO_PC.B6 | length 30.2
  Top Layer w0.145: v1(196.687,126.566) 196.837,126.716 TO_PC.B6@196.837,127.651 ; CN8.5@198.857,101.606 197.587,102.876 197.587,126.266 v1(197.887,126.566) ; v1(197.887,126.566) 197.887,127.601 TO_PC.A6@197.837,127.651 197.837,126.616 v1(197.887,126.566)
  Bottom Layer w0.145: v1(196.687,126.566) v1(197.887,126.566)
DP2: CN9.5 CN10.5 DC/AUX.A6 DC/AUX.B6 | length 36.1
  Top Layer w0.145: CN10.5@196.317,56.026 197.338,55.006 DC/AUX.A6@197.337,47.581 ; 198.337,47.581 198.387,47.631 v1(198.387,48.666)
  Bottom Layer w0.145: CN9.5@196.317,80.026 197.487,78.856 197.487,57.196 CN10.5@196.317,56.026 ; v1(197.187,48.666) v1(198.387,48.666)
F3_1: F3.1 FCAN1.1 J3.1 | length 26.5
  Top Layer w0.3: J3.1@154.516,90.297 155.786,91.567 157.788,91.567 159.586,89.766 162.088,89.766 165.088,92.766 168.637,92.766 ; 168.408,92.766 168.837,92.766 169.937,91.666 169.937,90.216 171.285,88.867 FCAN1.1@174.138,88.867 ; F3.1@174.187,87.166 FCAN1.1@174.187,88.818
FCAN_1: F2.1 FCAN.1 J2.1 | length 21.2
  Top Layer w0.145: F2.1@172.787,103.566 173.587,103.566 174.438,102.715 FCAN.1@174.437,101.566
  Top Layer w0.5: J2.1@156.757,108.396 162.058,108.397 164.102,106.351 165.517,106.351 166.402,105.466 170.988,105.466 172.787,103.665 F2.1@172.787,103.566
FCAN_2: FCAN.2 R71.1 | length 1.7
  Top Layer w0.145: R71.1@171.087,101.566 FCAN.2@172.737,101.566
FGNSS_2: FGNSS.2 R64.1 | length 1.8
  Top Layer w0.145: FGNSS.2@67.137,49.666 67.137,48.116 R64.1@67.287,47.966
FINP_2: FINP.2 R73.1 | length 2
  Top Layer w0.145: FINP.2@67.637,89.166 R73.1@69.687,89.166
FROT_2: FROT.2 R75.1 | length 1.6
  Top Layer w0.145: FROT.2@186.637,70.166 186.787,70.316 R75.1@186.787,71.666
FSER_2: FSER.2 R76.2 | length 1.6
  Top Layer w0.145: FSER.2@175.837,110.666 R76.2@177.487,110.666
FWAS_2: FWAS.2 R74.1 | length 1.6
  Top Layer w0.145: R74.1@67.387,106.666 67.537,106.516 FWAS.2@67.537,105.166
